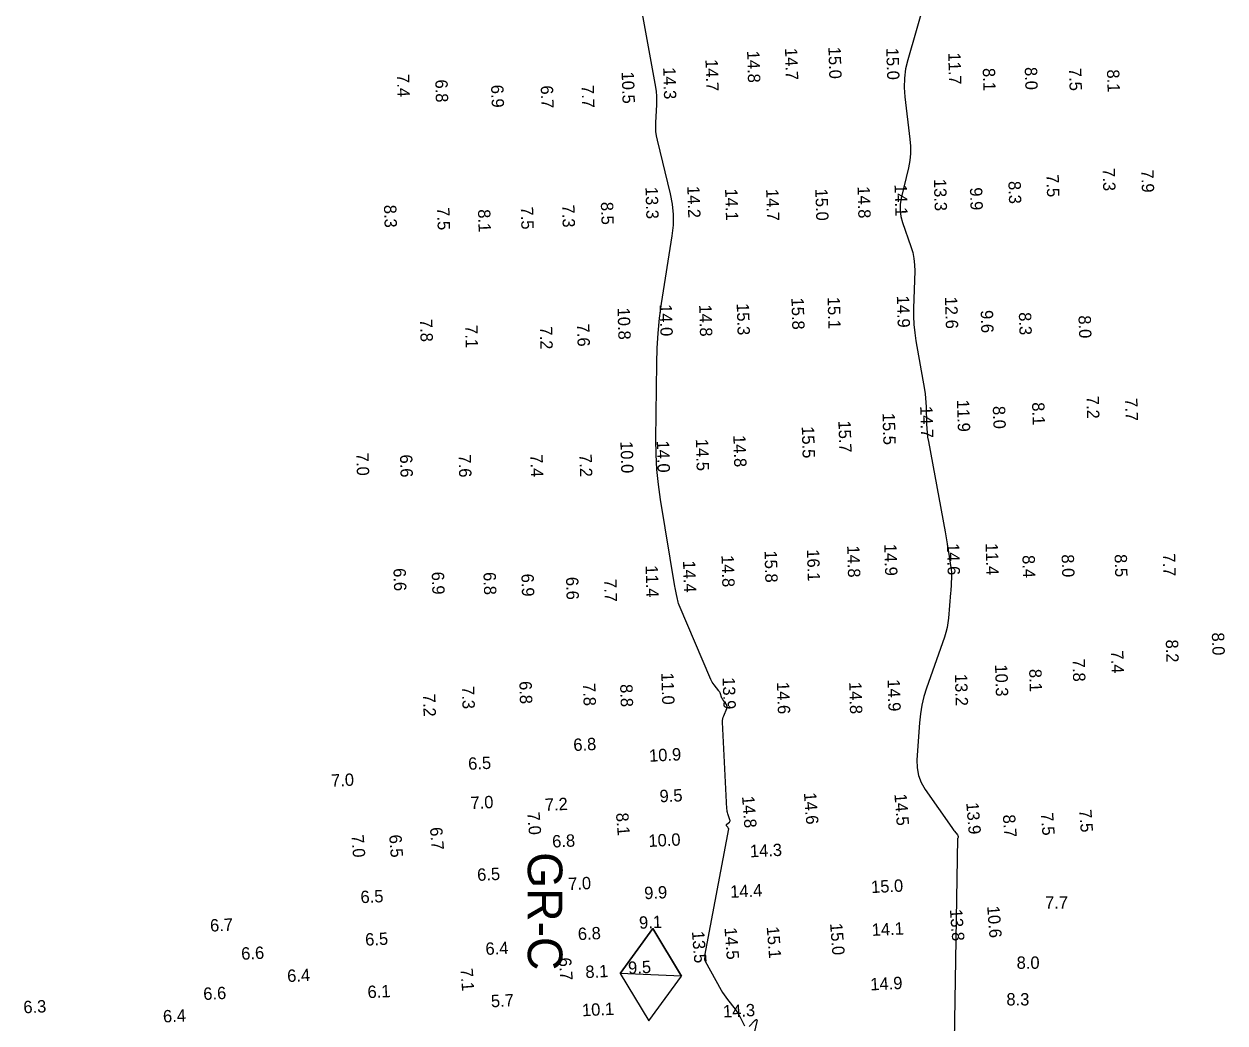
# Model space of a CAD drawing. Extents: x 824616 to 827440, y 158441 to 163197.
# Drawn here: x 825396.8 to 825883, y 161715.6 to 162120 of the extents above; entities that cross this region are included whole.
import ezdxf

# ---------------------------------------------------------------- set-up
doc = ezdxf.new("R2010")
doc.units = 0
for name, color, linetype in [('V-CHAN-CONT-EL14', 7, 'Continuous'), ('V-CHAN-NAID', 7, 'Continuous'), ('V-TOPO-SOUN', 7, 'Continuous')]:
    doc.layers.add(name, color=color, linetype=linetype)

msp = doc.modelspace()

# ---------------------------------------------------------------- linework, layer by layer
at = {"layer": 'V-CHAN-CONT-EL14'}
for points in [[(825672.47, 161742.77), (825682.09, 161794.12), (825682.03, 161794.3), (825681.95, 161794.48), (825681.85, 161794.65), (825681.74, 161794.82), (825681.27, 161795.46), (825681.19, 161795.61), (825681.17, 161795.76), (825681.22, 161795.9), (825681.34, 161796.04), (825682.36, 161796.93), (825682.54, 161797.14), (825682.64, 161797.36), (825682.66, 161797.61), (825682.61, 161797.88), (825681.8, 161800.26), (825681.65, 161800.75), (825681.53, 161801.25), (825681.45, 161801.76), (825681.41, 161802.28), (825679.59, 161837.32), (825679.6, 161838), (825679.68, 161838.66), (825679.84, 161839.32), (825680.08, 161839.96), (825681.36, 161842.89), (825681.49, 161843.31), (825681.5, 161843.72), (825681.4, 161844.11), (825681.17, 161844.49), (825679.93, 161846.15), (825679.72, 161846.45), (825679.53, 161846.77), (825679.38, 161847.1), (825679.25, 161847.44), (825678.77, 161848.84), (825678.64, 161849.18), (825678.48, 161849.5), (825678.3, 161849.82), (825678.08, 161850.11), (825676.18, 161852.5), (825675.8, 161853.01), (825675.46, 161853.54), (825675.16, 161854.08), (825674.89, 161854.66), (825662.07, 161884.74), (825661.83, 161885.35), (825661.62, 161885.96), (825661.45, 161886.58), (825661.31, 161887.21), (825660.81, 161889.76), (825660.69, 161890.4), (825660.58, 161891.04), (825660.46, 161891.68), (825660.36, 161892.32), (825654.53, 161927.5), (825653.66, 161933.59), (825653.05, 161939.7), (825652.72, 161945.83), (825652.65, 161951.98), (825652.96, 161982.71), (825653.14, 161988.77), (825653.53, 161994.81), (825654.13, 162000.84), (825654.96, 162006.84), (825659.24, 162034.28), (825659.69, 162038.54), (825659.72, 162042.79), (825659.33, 162047.02), (825658.52, 162051.23), (825653.23, 162072.93), (825652.87, 162074.69), (825652.65, 162076.46), (825652.55, 162078.24), (825652.59, 162080.03), (825653, 162087.23), (825653.05, 162089.03), (825652.99, 162090.82), (825652.83, 162092.6), (825652.57, 162094.38), (825645.63, 162133.12)], [(825761.59, 162130.07), (825754.57, 162105.52), (825753.7, 162101.8), (825753.22, 162098.05), (825753.11, 162094.27), (825753.39, 162090.46), (825755.47, 162073.41), (825755.7, 162070.47), (825755.67, 162067.55), (825755.38, 162064.65), (825754.83, 162061.75), (825751.93, 162049.44), (825751.53, 162046.95), (825751.48, 162044.48), (825751.79, 162042.04), (825752.46, 162039.61), (825755.86, 162029.93), (825756.59, 162027.49), (825757.09, 162025.02), (825757.36, 162022.51), (825757.4, 162019.96), (825756.95, 162005), (825756.94, 162001.65), (825757.09, 161998.32), (825757.41, 161995), (825757.9, 161991.7), (825761.32, 161971.99), (825761.59, 161970.25), (825761.79, 161968.51), (825761.93, 161966.76), (825762.01, 161965), (825762.2, 161957.97), (825762.28, 161956.21), (825762.43, 161954.46), (825762.64, 161952.72), (825762.93, 161950.99), (825769.68, 161914.34), (825769.98, 161912.73), (825770.26, 161911.12), (825770.53, 161909.51), (825770.79, 161907.9), (825772.05, 161899.92), (825772.16, 161899.07), (825772.23, 161898.22), (825772.27, 161897.37), (825772.26, 161896.51), (825772.15, 161893.08), (825772.12, 161892.22), (825772.07, 161891.37), (825772.02, 161890.51), (825771.95, 161889.66), (825771.11, 161879.52), (825770.88, 161877.56), (825770.53, 161875.62), (825770.06, 161873.71), (825769.46, 161871.83), (825762.21, 161851.19), (825761.13, 161847.75), (825760.29, 161844.27), (825759.69, 161840.73), (825759.33, 161837.15), (825758.33, 161822.07), (825758.37, 161818.86), (825758.94, 161815.8), (825760.03, 161812.88), (825761.65, 161810.11), (825772.41, 161794.66), (825772.67, 161794.28), (825772.94, 161793.92), (825773.22, 161793.56), (825773.51, 161793.2), (825774.68, 161791.79), (825774.91, 161791.43), (825774.99, 161791.07), (825774.95, 161790.69), (825774.83, 161790.45)], [(825772.26, 161634.63), (825774.83, 161790.45)], [(825672.47, 161742.77), (825672.38, 161742.43), (825672.36, 161741.78), (825672.34, 161741.21), (825672.59, 161740.56), (825679.04, 161728.91), (825679.62, 161727.92), (825680.23, 161726.95), (825680.89, 161726.01), (825681.58, 161725.09), (825684.69, 161721.13), (825685.25, 161720.39), (825685.77, 161719.62), (825686.26, 161718.83), (825686.71, 161718.01), (825688.55, 161714.5)], [(825690.44, 161714.22), (825692.7, 161716.56), (825693.18, 161716.97), (825693.46, 161717.03), (825693.56, 161716.76), (825693.47, 161716.14), (825684.63, 161678.21)]]:
    msp.add_lwpolyline(points, dxfattribs=at)
at = {"layer": 'V-CHAN-NAID'}
for points in [[(825649.77, 161716.43), (825663.04, 161734.57), (825651.4, 161753.79), (825638.13, 161735.66)], [(825663.04, 161734.57), (825638.13, 161735.66), (825651.4, 161753.79)]]:
    msp.add_lwpolyline(points, close=True, dxfattribs=at)

# ---------------------------------------------------------------- texts
msp.add_text('GR-C', height=14, rotation=270, dxfattribs=at).set_placement((825600.76, 161784.75))
at = {"layer": 'V-TOPO-SOUN'}
for s, rotation, p in [('14.7 ', 271.8, (825704.88, 162110.21)), ('15.0 ', 271.8, (825722.44, 162110.69)), ('15.0 ', 271.8, (825745.86, 162110.28)), ('14.7 ', 271.8, (825672.66, 162105.68)), ('14.8 ', 271.8, (825689.53, 162109.1)), ('11.7 ', 271.8, (825770.93, 162108.36)), ('7.4', 271.8, (825547.76, 162099.64)), ('10.5 ', 271.8, (825638.75, 162100.64)), ('14.3 ', 271.8, (825655.54, 162102.42)), ('8.1', 271.8, (825784.92, 162102.09)), ('8.0', 271.8, (825801.94, 162102.49)), ('7.5', 271.8, (825819.84, 162102.11)), ('8.1', 271.8, (825835.22, 162101.52)), ('6.8', 271.8, (825563.29, 162097.43)), ('6.9', 271.8, (825585.9, 162095.31)), ('6.7', 271.8, (825605.98, 162095.04)), ('7.7', 271.8, (825622.51, 162095.2)), ('7.3', 271.8, (825833.45, 162061.56)), ('7.9', 271.8, (825849.08, 162060.93)), ('13.3 ', 271.8, (825765.13, 162057.2)), ('8.3', 271.8, (825795.32, 162056.35)), ('7.5', 271.8, (825810.71, 162059.09)), ('13.3 ', 271.8, (825648.38, 162053.97)), ('14.2 ', 271.8, (825665.33, 162054.36)), ('14.1 ', 271.8, (825680.61, 162053.32)), ('14.7 ', 271.8, (825697.23, 162053.15)), ('15.0 ', 271.8, (825717.14, 162053.26)), ('14.8 ', 271.8, (825734.22, 162054.22)), ('14.1 ', 271.8, (825749.19, 162055.09)), ('9.9', 271.8, (825779.73, 162053.77)), ('8.3', 271.8, (825542.54, 162046.71)), ('7.3', 271.8, (825614.64, 162046.8)), ('8.5', 271.8, (825630.33, 162047.9)), ('7.5', 271.8, (825564.03, 162045.72)), ('8.1', 271.8, (825580.59, 162044.92)), ('7.5', 271.8, (825597.91, 162046.01)), ('15.8 ', 271.8, (825707.46, 162009.16)), ('15.1 ', 271.8, (825722.1, 162009.47)), ('14.9 ', 271.8, (825750.14, 162009.98)), ('12.6 ', 271.8, (825769.63, 162009.51)), ('10.8 ', 271.8, (825637.07, 162005.09)), ('14.0 ', 271.8, (825654.09, 162006.5)), ('14.8 ', 271.8, (825670.11, 162006.38)), ('15.3 ', 271.8, (825685.32, 162006.91)), ('9.6', 271.8, (825784.09, 162004.08)), ('8.3', 271.8, (825799.55, 162003.24)), ('7.8', 271.8, (825557.1, 162000.51)), ('7.1', 271.8, (825575.4, 161998.04)), ('7.2', 271.8, (825605.62, 161997.45)), ('7.6', 271.8, (825620.67, 161998.61)), ('8.0', 271.8, (825823.7, 162001.97)), ('7.2', 271.8, (825826.93, 161969.37)), ('7.7', 271.8, (825842.54, 161968.45)), ('14.7 ', 271.8, (825759.58, 161965.26)), ('11.9 ', 271.8, (825774.47, 161967.82)), ('8.0', 271.8, (825789.01, 161965.29)), ('8.1', 271.8, (825804.9, 161966.8)), ('15.7 ', 271.8, (825726.48, 161959.41)), ('15.5 ', 271.8, (825744.34, 161962.52)), ('15.5 ', 271.8, (825711.66, 161957.11)), ('10.0 ', 271.8, (825638.23, 161951.05)), ('14.0 ', 271.8, (825652.95, 161951.31)), ('14.5 ', 271.8, (825668.77, 161951.97)), ('14.8 ', 271.8, (825683.96, 161953.51)), ('7.0', 271.8, (825531.31, 161946.33)), ('6.6', 271.8, (825548.99, 161945.65)), ('7.6', 271.8, (825572.72, 161945.64)), ('7.4', 271.8, (825601.78, 161945.73)), ('7.2', 271.8, (825621.65, 161945.84)), ('15.8 ', 271.8, (825696.57, 161906.77)), ('16.1 ', 271.8, (825713.75, 161907.28)), ('14.8 ', 271.8, (825730.03, 161908.84)), ('14.9 ', 271.8, (825745.04, 161909.5)), ('14.6 ', 271.8, (825770.38, 161909.77)), ('11.4 ', 271.8, (825786.07, 161909.79)), ('8.0', 271.8, (825816.85, 161905.23)), ('8.5', 271.8, (825838.3, 161905.31)), ('7.7', 271.8, (825857.83, 161905.59)), ('11.4 ', 271.8, (825648.42, 161900.78)), ('14.4 ', 271.8, (825663.59, 161902.75)), ('14.8 ', 271.8, (825679.15, 161904.94)), ('8.4', 271.8, (825801, 161904.93)), ('6.6', 271.8, (825546.37, 161899.64)), ('6.9', 271.8, (825561.87, 161898.21)), ('6.8', 271.8, (825582.81, 161898.07)), ('6.9', 271.8, (825598.15, 161897.41)), ('6.6', 271.8, (825616.21, 161896.1)), ('7.7', 271.8, (825631.67, 161895.23)), ('8.0', 271.8, (825877.68, 161873.61)), ('7.4', 271.8, (825836.86, 161866.33)), ('8.2', 271.8, (825859.03, 161870.74)), ('7.8', 271.8, (825821.27, 161862.95)), ('11.0 ', 271.8, (825654.8, 161857.37)), ('13.2 ', 271.8, (825773.64, 161856.84)), ('10.3 ', 271.8, (825789.9, 161860.68)), ('8.1', 271.8, (825803.73, 161858.86)), ('7.3', 271.8, (825574.08, 161851.89)), ('6.8', 271.8, (825597.34, 161853.93)), ('7.8', 271.8, (825623.11, 161853.13)), ('8.8', 271.8, (825638.15, 161852.7)), ('13.9 ', 271.8, (825679.61, 161855.49)), ('14.6 ', 271.8, (825701.62, 161853.55)), ('14.8 ', 271.8, (825730.84, 161853.58)), ('14.9 ', 271.8, (825746.38, 161854.66)), ('7.2', 271.8, (825558.32, 161848.78)), ('6.8', 2.7, (825619.31, 161825.67)), ('6.5', 2.7, (825576.74, 161818.04)), ('10.9 ', 2.7, (825649.97, 161821.32)), ('7.0', 2.7, (825521.24, 161811.22)), ('9.5', 2.7, (825654.22, 161804.9)), ('14.6 ', 274.5, (825712.52, 161808.76)), ('14.5 ', 274.5, (825749.16, 161808.26)), ('7.0', 2.7, (825577.67, 161802.16)), ('7.2', 2.7, (825607.77, 161801.41)), ('14.8 ', 274.5, (825687.47, 161807.34)), ('13.9 ', 274.5, (825778.26, 161804.74)), ('7.0', 274.5, (825600.54, 161800.83)), ('8.1', 274.5, (825636.46, 161800.53)), ('8.7', 274.5, (825793.05, 161799.79)), ('7.5', 274.5, (825808.44, 161800.58)), ('7.5', 274.5, (825823.93, 161801.85)), ('6.7', 274.5, (825561.15, 161794.69)), ('7.0', 274.5, (825529.32, 161791.67)), ('6.5', 274.5, (825544.62, 161791.67)), ('6.8', 2.7, (825610.75, 161786.59)), ('10.0 ', 2.7, (825649.71, 161786.83)), ('14.3 ', 2.7, (825690.79, 161782.64)), ('6.5', 2.7, (825580.38, 161773.09)), ('7.0', 2.7, (825617.21, 161769.37)), ('15.0 ', 2.7, (825739.84, 161768.17)), ('6.5', 2.7, (825533.14, 161764.07)), ('9.9', 2.7, (825648.02, 161765.67)), ('14.4 ', 2.7, (825682.79, 161766.24)), ('9.1', 2.7, (825645.92, 161753.69)), ('13.8 ', 274.5, (825771.62, 161761.54)), ('10.6 ', 274.5, (825786.71, 161762.83)), ('6.7', 2.7, (825472.24, 161752.56)), ('6.8', 2.7, (825621.15, 161749.12)), ('15.1 ', 274.5, (825697.46, 161754.48)), ('15.0 ', 274.5, (825723.11, 161755.86)), ('14.1 ', 2.7, (825740.11, 161750.82)), ('6.5', 2.7, (825535.05, 161746.86)), ('13.5 ', 274.5, (825667.2, 161752.63)), ('14.5 ', 274.5, (825680.37, 161754.07)), ('6.6', 2.7, (825484.87, 161741.17)), ('6.4', 2.7, (825583.74, 161743.13)), ('6.7', 274.5, (825613.3, 161741.89)), ('9.5', 2.7, (825641.48, 161735.42)), ('6.4', 2.7, (825503.47, 161732.16)), ('7.1', 274.5, (825573.46, 161737.59)), ('8.1', 2.7, (825624.18, 161733.76)), ('6.6', 2.7, (825469.5, 161724.89)), ('6.1', 2.7, (825535.99, 161725.64)), ('14.9 ', 2.7, (825739.54, 161728.77)), ('5.7', 2.7, (825585.94, 161721.94)), ('6.3', 2.7, (825396.66, 161719.5)), ('6.4', 2.7, (825453.19, 161715.77)), ('10.1 ', 2.7, (825622.82, 161718.29)), ('14.3 ', 2.7, (825679.9, 161717.78))]:
    msp.add_text(s, height=5, rotation=rotation, dxfattribs=at).set_placement(p)
for s, p in [('7.7', (825810.17, 161761.86)), ('8.0', (825798.66, 161737.52)), ('8.3', (825794.52, 161722.69))]:
    msp.add_text(s, height=5, dxfattribs=at).set_placement(p)

doc.saveas('drawing.dxf')
